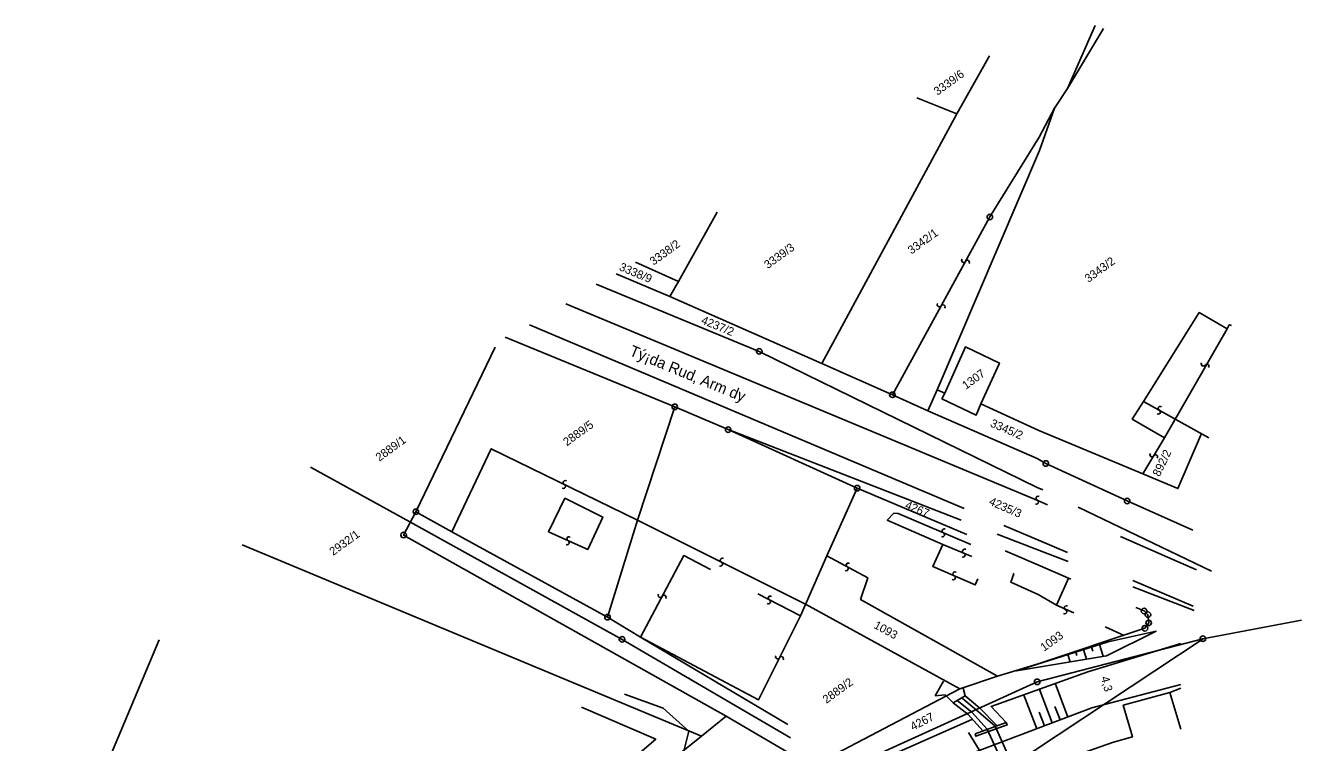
# Model space of a CAD drawing. Extents: x -658910 to -658078, y -1170373 to -1169331.
# Drawn here: x -658308.5 to -658078.2, y -1169460.8 to -1169331.4 of the extents above; entities that cross this region are included whole.
import ezdxf

# ---------------------------------------------------------------- set-up
doc = ezdxf.new("R2010")
doc.units = 0
for name, color, linetype in [('Vrstva 1', 7, 'Continuous'), ('Vrstva 10', 7, 'Continuous'), ('Vrstva 11', 7, 'Continuous'), ('Vrstva 26', 7, 'Continuous'), ('Vrstva 6', 7, 'Continuous'), ('Vrstva 8', 7, 'Continuous'), ('Vrstva 9', 7, 'Continuous')]:
    doc.layers.add(name, color=color, linetype=linetype)

msp = doc.modelspace()

# ---------------------------------------------------------------- linework, layer by layer
at = {"layer": 'Vrstva 1'}
for p, q in [((-658096.07, -1169442.051), (-658095.97, -1169442.051)), ((-658125.98, -1169449.82), (-658125.88, -1169449.82))]:
    msp.add_line(p, q, dxfattribs=at)
for points in [[(-658125.93, -1169449.82), (-658096.02, -1169442.051), (-658078.211, -1169438.67)], [(-658206.289, -1169500.25), (-658202.641, -1169496.621), (-658158.738, -1169464.74), (-658125.93, -1169449.82)]]:
    msp.add_lwpolyline(points, dxfattribs=at)
for centre in [(-658096.02, -1169442.051), (-658125.93, -1169449.82)]:
    msp.add_circle(centre, 0.499, dxfattribs=at)
at = {"layer": 'Vrstva 10'}
msp.add_lwpolyline([(-658129.674, -1169447.813), (-658113.092, -1169442.589), (-658104.448, -1169440.711), (-658113.419, -1169445.118)], close=True, dxfattribs=at)
for points in [[(-658100, -1169442.93), (-658116.79, -1169448.035), (-658134.23, -1169454.268), (-658131.498, -1169457.166)], [(-658117.533, -1169443.988), (-658116.99, -1169445.71)], [(-658116.102, -1169443.538), (-658115.859, -1169444.307)], [(-658114.671, -1169443.086), (-658114.001, -1169445.214)], [(-658120.394, -1169444.89), (-658119.979, -1169446.206)], [(-658118.963, -1169444.439), (-658118.772, -1169445.046)], [(-658276.584, -1169590.485), (-658256.68, -1169559.896), (-658245.84, -1169545.609), (-658230.723, -1169528.912), (-658213.416, -1169511.695), (-658194.942, -1169496.127), (-658183.568, -1169487.746), (-658168.721, -1169477.939), (-658152.051, -1169468.653), (-658137.192, -1169462.524), (-658116.058, -1169454.53), (-658100, -1169450.302)], [(-658272.892, -1169597.713), (-658264.789, -1169582.869), (-658255.603, -1169568.821), (-658244.243, -1169553.949), (-658226.467, -1169533.172), (-658204.621, -1169512.867), (-658189.065, -1169500.683), (-658177.28, -1169492.406), (-658159.62, -1169480.938), (-658148.705, -1169475.017), (-658136.322, -1169469.204), (-658112.115, -1169460.739), (-658108.733, -1169459.765), (-658110.378, -1169454.042), (-658101.99, -1169451.722), (-658100, -1169450.993)], [(-658188.159, -1169449.626), (-658188.772, -1169449.146)], [(-658123.202, -1169457.232), (-658125.542, -1169451.047)], [(-658120.396, -1169456.171), (-658122.704, -1169450.07)], [(-658189.788, -1169462.569), (-658188.806, -1169458.731), (-658193.421, -1169454.548), (-658200.403, -1169452.046)], [(-658144.313, -1169452.336), (-658142.554, -1169452.16), (-658141.068, -1169453.603)], [(-658126.008, -1169458.294), (-658128.38, -1169452.024)], [(-658101.99, -1169451.722), (-658100, -1169458.386)], [(-658208.185, -1169454.401), (-658194.776, -1169460.194), (-658224.927, -1169485.893)], [(-658124.605, -1169457.763), (-658125.547, -1169455.272)], [(-658121.799, -1169456.702), (-658122.729, -1169454.245)], [(-658137.695, -1169456.646), (-658152.911, -1169463.386), (-658171.698, -1169473.069), (-658186.816, -1169484.99), (-658193.967, -1169490.9), (-658193.37, -1169491.788), (-658197.029, -1169494.358), (-658197.792, -1169493.244), (-658216.175, -1169508.98), (-658236.592, -1169530.379), (-658247.771, -1169542.617), (-658259.683, -1169558.947), (-658278.256, -1169587.533)]]:
    msp.add_lwpolyline(points, dxfattribs=at)
at = {"layer": 'Vrstva 26'}
msp.add_lwpolyline([(-658138.325, -1169458.989), (-658123.558, -1169482.912), (-658117.484, -1169496.823)], dxfattribs=at)
at = {"layer": 'Vrstva 6'}
for p, q in [((-658144.313, -1169452.336), (-658142.816, -1169449.708)), ((-658139.308, -1169450.953), (-658138.895, -1169452.367)), ((-658142.554, -1169452.16), (-658144.313, -1169452.336)), ((-658141.068, -1169453.603), (-658142.554, -1169452.16)), ((-658138.895, -1169452.367), (-658141.068, -1169453.603)), ((-658137.697, -1169455.292), (-658140.349, -1169453.195)), ((-658136.949, -1169454.88), (-658139.486, -1169452.791)), ((-658136.289, -1169454.546), (-658138.895, -1169452.367)), ((-658138.385, -1169455.719), (-658141.068, -1169453.603))]:
    msp.add_line(p, q, dxfattribs=at)
for points in [[(-658135.753, -1169458.672), (-658138.385, -1169455.719)], [(-658134.969, -1169458.369), (-658137.697, -1169455.292)], [(-658136.949, -1169454.88), (-658133.522, -1169457.81)], [(-658133.189, -1169457.712), (-658136.289, -1169454.546)], [(-658133.522, -1169457.81), (-658122.215, -1169483.212)], [(-658134.969, -1169458.369), (-658123.366, -1169483.692)]]:
    msp.add_lwpolyline(points, dxfattribs=at)
msp.add_lwpolyline([(-658137.129, -1169459.211), (-658136.975, -1169459.634), (-658131.336, -1169457.586), (-658131.498, -1169457.166)], close=True, dxfattribs=at)
at = {"layer": 'Vrstva 8'}
for p, q in [((-658134.511, -1169365.949), (-658134.411, -1169365.949)), ((-658192.23, -1169380.33), (-658192.23, -1169380.33)), ((-658176.14, -1169390.199), (-658176.04, -1169390.199)), ((-658152.109, -1169398.031), (-658152.009, -1169398.031)), ((-658152.109, -1169398.031), (-658152.009, -1169398.031)), ((-658191.39, -1169400.199), (-658191.29, -1169400.199)), ((-658191.39, -1169400.199), (-658191.29, -1169400.199)), ((-658181.761, -1169404.32), (-658181.661, -1169404.32)), ((-658181.761, -1169404.32), (-658181.661, -1169404.32)), ((-658124.402, -1169410.43), (-658124.302, -1169410.43)), ((-658158.46, -1169414.879), (-658158.36, -1169414.879)), ((-658158.46, -1169414.879), (-658158.36, -1169414.879)), ((-658109.73, -1169417.191), (-658109.63, -1169417.191)), ((-658238.12, -1169419.129), (-658238.02, -1169419.129)), ((-658238.12, -1169419.129), (-658238.02, -1169419.129)), ((-658204.352, -1169420.1), (-658204.352, -1169420.1)), ((-658240.339, -1169423.34), (-658240.239, -1169423.34)), ((-658214.129, -1169422.76), (-658214.129, -1169422.76)), ((-658207.059, -1169425.961), (-658207.059, -1169425.961)), ((-658106.679, -1169437.039), (-658106.579, -1169437.039)), ((-658203.538, -1169438.15), (-658203.438, -1169438.15)), ((-658203.538, -1169438.15), (-658203.438, -1169438.15)), ((-658105.972, -1169437.711), (-658105.872, -1169437.711)), ((-658105.839, -1169439.191), (-658105.739, -1169439.191)), ((-658106.519, -1169440.16), (-658106.419, -1169440.16)), ((-658200.902, -1169442.16), (-658200.802, -1169442.16))]:
    msp.add_line(p, q, dxfattribs=at)
for points in [[(-658125.52, -1169353.961), (-658122.801, -1169346.34), (-658120.441, -1169342.801), (-658115.441, -1169331.41)], [(-658120.441, -1169342.801), (-658113.922, -1169331.961)], [(-658134.5, -1169336.859), (-658140.441, -1169347.359), (-658147.648, -1169344.449)], [(-658140.441, -1169347.359), (-658164.77, -1169392.371)], [(-658122.801, -1169346.34), (-658125.59, -1169351.58)], [(-658125.59, -1169351.58), (-658134.461, -1169365.949), (-658152.059, -1169398.031)], [(-658143.988, -1169397.121), (-658125.52, -1169353.961)], [(-658190.691, -1169377.6), (-658183.699, -1169365.059)], [(-658192.23, -1169380.33), (-658190.691, -1169377.6), (-658198.43, -1169374.109)], [(-658201.91, -1169376.199), (-658192.23, -1169380.33), (-658164.77, -1169392.371), (-658152.059, -1169398.031), (-658145.66, -1169400.941), (-658125.941, -1169409.551)], [(-658125.91, -1169414.74), (-658176.09, -1169390.199), (-658205.559, -1169378.059)], [(-658211.02, -1169381.621), (-658125.691, -1169417.141)], [(-658090.843, -1169385.561), (-658091.25, -1169385.391), (-658091.629, -1169386.15), (-658096.68, -1169383.199), (-658106.711, -1169399.23), (-658108.77, -1169402.41), (-658102.922, -1169405.789)], [(-658139.104, -1169418.577), (-658217.559, -1169385.391)], [(-658091.629, -1169386.15), (-658102.922, -1169405.789)], [(-658181.711, -1169404.32), (-658191.34, -1169400.199), (-658221.961, -1169387.66)], [(-658223.789, -1169389.449), (-658238.07, -1169419.129), (-658240.289, -1169423.34), (-658182.059, -1169455.99), (-658166.07, -1169465.391)], [(-658125.641, -1169404.49), (-658136.09, -1169399.67), (-658132.738, -1169392.32), (-658138.879, -1169389.391), (-658142.602, -1169397.75), (-658143.121, -1169398.74), (-658136.941, -1169401.73), (-658136.09, -1169399.67)], [(-658142.602, -1169397.75), (-658143.988, -1169397.121), (-658145.66, -1169400.941)], [(-658191.34, -1169400.199), (-658198.07, -1169420.68), (-658203.488, -1169438.15), (-658197.531, -1169441.76), (-658189.719, -1169427.059), (-658184.876, -1169429.552)], [(-658106.711, -1169399.23), (-658094.93, -1169405.801)], [(-658139.654, -1169420.641), (-658181.711, -1169404.32), (-658158.41, -1169414.879)], [(-658096.27, -1169404.99), (-658100.531, -1169414.969), (-658106.828, -1169412.281), (-658125.641, -1169404.49)], [(-658106.828, -1169412.281), (-658102.922, -1169405.789)], [(-658139.891, -1169451.109), (-658167.762, -1169435.789), (-658198.07, -1169420.68), (-658224.469, -1169407.77), (-658231.559, -1169422.76)], [(-658125.941, -1169409.551), (-658124.352, -1169410.43), (-658109.68, -1169417.191), (-658097.826, -1169422.434)], [(-658170.473, -1169459.944), (-658200.852, -1169442.16), (-658239.148, -1169420.961), (-658257.102, -1169411.109)], [(-658133.059, -1169448.781), (-658157.789, -1169434.969), (-658156.52, -1169431.09), (-658163.898, -1169427.1), (-658158.41, -1169414.879), (-658138.646, -1169423.268)], [(-658124.928, -1169415.212), (-658125.91, -1169414.74)], [(-658125.691, -1169417.141), (-658124.045, -1169417.86)], [(-658094.474, -1169429.853), (-658118.541, -1169418.283)], [(-658238.07, -1169419.129), (-658231.559, -1169422.76), (-658203.488, -1169438.15)], [(-658137.894, -1169425.032), (-658151.039, -1169419.43), (-658151.789, -1169419.379), (-658153, -1169420.641), (-658142.949, -1169425.02), (-658137.691, -1169427.205)], [(-658125.512, -1169426.129), (-658133.116, -1169423.178)], [(-658125.691, -1169424.25), (-658131.921, -1169421.615)], [(-658110.894, -1169423.605), (-658102.391, -1169427.32), (-658097.145, -1169429.637)], [(-658269.449, -1169425.1), (-658186.52, -1169459.621)], [(-658142.949, -1169425.02), (-658144.738, -1169429.031), (-658137.09, -1169432.35), (-658136.629, -1169431.225)], [(-658125.691, -1169424.25), (-658120.462, -1169426.482)], [(-658168.66, -1169437.9), (-658163.898, -1169427.1)], [(-658131.714, -1169426.21), (-658125.82, -1169428.711)], [(-658125.512, -1169426.129), (-658120.339, -1169428.136)], [(-658130.344, -1169430.259), (-658130.148, -1169430.34), (-658130.68, -1169431.84), (-658125.762, -1169434.07)], [(-658119.859, -1169431.298), (-658125.82, -1169428.711)], [(-658122.43, -1169436), (-658120.191, -1169431.02)], [(-658108.666, -1169432.666), (-658097.61, -1169436.956)], [(-658108.657, -1169431.521), (-658097.741, -1169436.181)], [(-658176.364, -1169433.934), (-658168.66, -1169437.9), (-658176.23, -1169453.09), (-658197.531, -1169441.76), (-658170.912, -1169457.542)], [(-658125.762, -1169434.07), (-658122.43, -1169436), (-658119.311, -1169437.398)], [(-658125.75, -1169446.57), (-658106.469, -1169440.16), (-658105.789, -1169439.191), (-658105.922, -1169437.711), (-658106.629, -1169437.039), (-658108.095, -1169436.403)], [(-658202.732, -1169511.222), (-658165.92, -1169484.904), (-658139.581, -1169470.905), (-658095.97, -1169442.051)], [(-658113.672, -1169439.926), (-658110.23, -1169441.469)], [(-658308.539, -1169500.27), (-658295.859, -1169469.441), (-658284.391, -1169442.24)], [(-658211.672, -1169500.27), (-658205.859, -1169495.359), (-658192.191, -1169485.07), (-658166.07, -1169465.391), (-658163.68, -1169463.92), (-658162.129, -1169462.75), (-658139.891, -1169451.109), (-658133.059, -1169448.781), (-658125.75, -1169446.57)], [(-658182.059, -1169455.99), (-658186.52, -1169459.621), (-658208.531, -1169477.24), (-658192.191, -1169485.07)]]:
    msp.add_lwpolyline(points, dxfattribs=at)
msp.add_lwpolyline([(-658211.191, -1169416.68), (-658214.129, -1169422.76), (-658207.059, -1169425.961), (-658204.352, -1169420.1)], close=True, dxfattribs=at)
for centre in [(-658134.461, -1169365.949), (-658176.09, -1169390.199), (-658152.059, -1169398.031), (-658152.059, -1169398.031), (-658191.34, -1169400.199), (-658191.34, -1169400.199), (-658181.711, -1169404.32), (-658181.711, -1169404.32), (-658124.352, -1169410.43), (-658158.41, -1169414.879), (-658158.41, -1169414.879), (-658109.68, -1169417.191), (-658238.07, -1169419.129), (-658238.07, -1169419.129), (-658240.289, -1169423.34), (-658106.629, -1169437.039), (-658105.922, -1169437.711), (-658203.488, -1169438.15), (-658203.488, -1169438.15), (-658106.469, -1169440.16), (-658105.789, -1169439.191), (-658200.852, -1169442.16)]:
    msp.add_circle(centre, 0.499, dxfattribs=at)
for centre, radius, start, end in [((-658139.186, -1169373.784), 0.376, 144.29318, 330.60432), ((-658138.528, -1169374.15), 0.377, 323.61714, 151.28036), ((-658143.589, -1169381.805), 0.376, 144.29834, 330.60947), ((-658142.931, -1169382.171), 0.377, 323.6223, 151.28551), ((-658095.941, -1169392.501), 0.376, 142.11182, 328.42295), ((-658095.297, -1169392.892), 0.377, 321.43578, 149.09899), ((-658103.683, -1169400.493), 0.376, 53.87538, 240.18652), ((-658104.054, -1169401.148), 0.377, 233.19934, 60.86256), ((-658105.199, -1169408.833), 0.376, 141.95506, 328.26619), ((-658104.556, -1169409.225), 0.377, 321.27901, 148.94223), ((-658211.439, -1169414.555), 0.376, 236.96601, 63.27714), ((-658211.104, -1169413.88), 0.377, 56.28997, 243.95318), ((-658125.747, -1169416.706), 0.376, 59.42568, 245.73682), ((-658126.052, -1169417.395), 0.377, 238.74964, 66.41286), ((-658143.003, -1169423.264), 0.376, 239.95221, 66.26334), ((-658142.704, -1169422.573), 0.377, 59.27617, 246.93938), ((-658210.761, -1169424.7), 0.376, 238.68426, 64.99539), ((-658210.446, -1169424.015), 0.377, 58.00821, 245.67143), ((-658139.016, -1169426.241), 0.377, 59.89399, 247.5572), ((-658182.741, -1169427.902), 0.377, 55.85131, 243.51453), ((-658139.307, -1169426.936), 0.376, 240.57003, 66.88116), ((-658183.081, -1169428.574), 0.376, 236.52736, 62.83849), ((-658160.393, -1169429.428), 0.376, 234.60394, 60.91507), ((-658160.031, -1169428.768), 0.377, 53.92789, 241.59111), ((-658140.76, -1169430.345), 0.377, 58.89687, 246.56009), ((-658141.063, -1169431.034), 0.376, 239.57291, 65.88405), ((-658193.951, -1169434.229), 0.376, 145.07023, 331.38136), ((-658193.288, -1169434.586), 0.377, 324.39419, 152.0574), ((-658174.45, -1169435.39), 0.376, 235.79764, 62.10877), ((-658174.101, -1169434.723), 0.377, 55.12159, 242.78481), ((-658120.965, -1169437.174), 0.377, 238.18471, 65.84792), ((-658120.652, -1169436.489), 0.376, 58.86075, 245.17188), ((-658172.775, -1169445.318), 0.376, 146.5598, 332.87094), ((-658172.103, -1169445.657), 0.377, 325.88376, 153.54698)]:
    msp.add_arc(centre, radius, start, end, dxfattribs=at)

# ---------------------------------------------------------------- texts
at = {"layer": 'Vrstva 11'}
msp.add_text('4,3', height=1.5, rotation=284.75094, dxfattribs=at).set_placement((-658114.424, -1169449.036))
at = {"layer": 'Vrstva 9'}
for s, height, rotation, p in [('3339/6', 1.5, 35.98794, (-658143.907, -1169344.096)), ('3342/1', 1.5, 35.98794, (-658148.608, -1169372.747)), ('3338/2', 1.5, 35.98794, (-658195.191, -1169374.755)), ('3339/3', 1.5, 35.98794, (-658174.54, -1169375.376)), ('3338/9', 1.5, 336.89079, (-658201.5, -1169375.5)), ('3343/2', 1.5, 35.98794, (-658116.67, -1169377.86)), ('4237/2', 1.5, 337.61628, (-658186.699, -1169385.129)), ('Tý¡da Rud‚ Arm\xa0dy', 1.99999, 337.61628, (-658199.691, -1169390.871)), ('1307', 1.5, 35.98794, (-658138.783, -1169397.141)), ('2889/5', 1.5, 35.98794, (-658210.81, -1169407.356)), ('3345/2', 1.5, 336.42369, (-658134.52, -1169403.699)), ('2889/1', 1.5, 35.98794, (-658244.669, -1169410.123)), ('892/2', 1.5, 64.00314, (-658103.838, -1169412.914)), ('4235/3', 1.5, 336.3948, (-658134.749, -1169417.804)), ('4267', 1.5, 336.99447, (-658149.902, -1169418.469)), ('2932/1', 1.5, 35.98794, (-658253.014, -1169427.124)), ('1093', 1.5, 331.21233, (-658155.539, -1169440.039)), ('1093', 1.5, 35.98794, (-658124.668, -1169444.402)), ('2889/2', 1.5, 35.98794, (-658163.968, -1169453.815)), ('4267', 1.5, 27.61299, (-658148.338, -1169458.676))]:
    msp.add_text(s, height=height, rotation=rotation, dxfattribs=at).set_placement(p)

doc.saveas('drawing.dxf')
